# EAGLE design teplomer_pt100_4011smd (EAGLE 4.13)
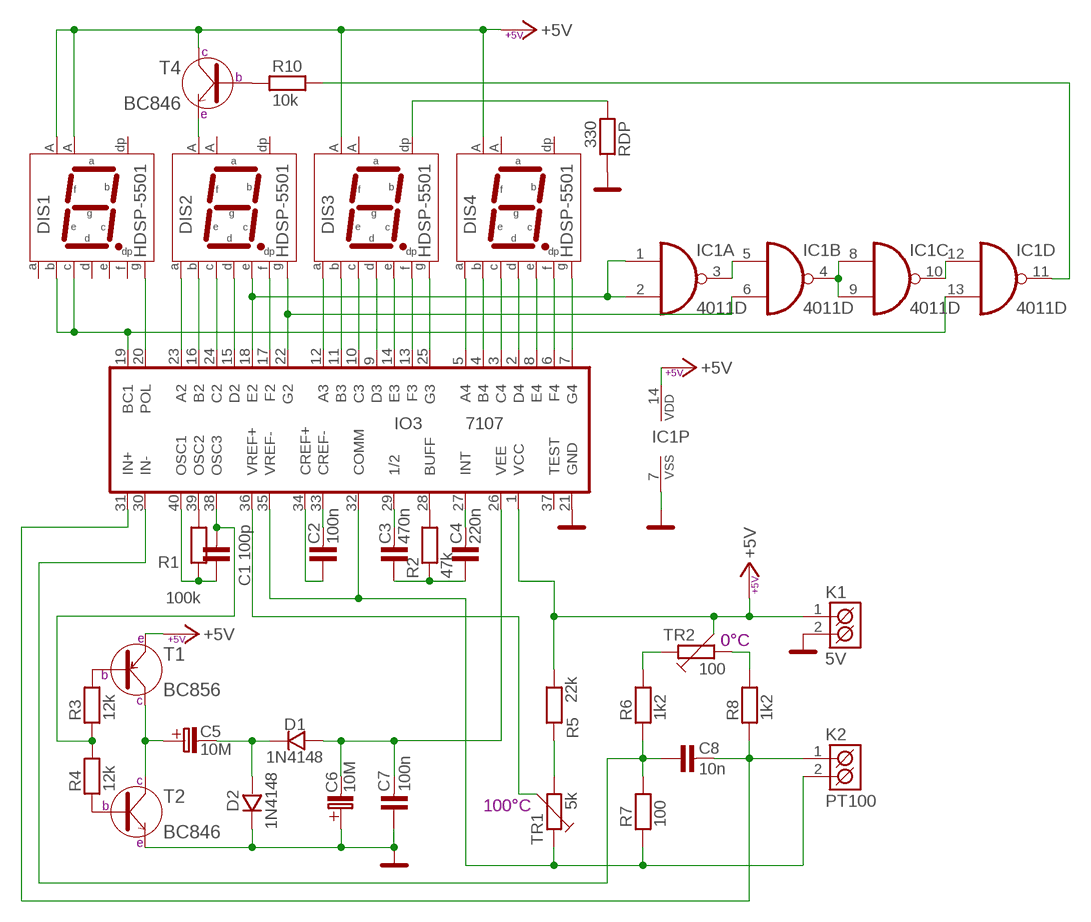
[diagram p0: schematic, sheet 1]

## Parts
C1  100p  C-KERAMIK_SMD_1206  [1206]
C2  100n  100N-J/63V  [RM5_2,5]
C3  470n  470N-J/63V  [RM5_3,2]
C4  220n  220N-J/63V  [RM5_3,2]
C5  10M  10M/25V  [C_EL_2]
C6  10M  10M/25V  [C_EL_2]
C7  100n  C-KERAMIK_SMD_1206  [1206]
C8  10n  C-KERAMIK_SMD_1206  [1206]
D1  1N4148  1N4148_SMD_SOD80  [SOD-80]
D2  1N4148  1N4148_SMD_SOD80  [SOD-80]
DIS1  HDSP-5501  [HDSP-M]
DIS2  HDSP-5501  [HDSP-M]
DIS3  HDSP-5501  [HDSP-M]
DIS4  HDSP-5501  [HDSP-M]
IC1  4011D  [SO14]
IO3  7107  [DIL40]
K1  5V  ARK500/2  [ARK500/2]
K2  PT100  ARK500/2  [ARK500/2]
R1  100k  R_SMD_1206  [1206]
R2  47k  R_SMD_1206  [1206]
R3  12k  R_SMD_1206  [1206]
R4  12k  R_SMD_1206  [1206]
R5  22k  R_SMD_1206  [1206]
R6  1k2  R_SMD_1206  [1206]
R7  100  R_SMD_1206  [1206]
R8  1k2  R_SMD_1206  [1206]
R10  10k  R_SMD_1206  [1206]
RDP  330  R_SMD_1206  [1206]
T1  BC856  [SOT-23]
T2  BC846  [SOT-23]
T4  BC846  [SOT-23]
TR1  5k  TRIMR64P  [64P]
TR2  100  TRIMR64P  [64P]

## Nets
+5V: DIS1.3(CA1) DIS1.8(CA2) DIS3.3(CA1) DIS4.3(CA1) IC1.14(P:VDD) IO3.1(VCC) K1.1(K1) R5.2 T1.1(E) T4.3(C) TR2.2
ANOD: IC1.11(D:O) R10.2
GND: C6.C+(C_EL+) C7.1 D2.K IC1.7(P:VSS) IO3.21(GND) K1.2(K2) RDP.2 T2.1(E)
N$1: IO3.39(OSC2) R1.2
N$2: C2.2 IO3.33(CREF-)
N$3: C1.2 IO3.38(OSC3) R3.1 R4.2
N$4: IO3.28(BUFF) R2.2
N$5: R3.2 T1.2(B)
N$6: R4.1 T2.2(B)
N$8: C5.C+(C_EL+) T1.3(C) T2.3(C)
N$9: IC1.10(C:O) IC1.12(D:I0)
N$10: DIS2.4(C) IO3.24(C2)
N$11: IC1.4(B:O) IC1.8(C:I0) IC1.9(C:I1)
N$12: C5.C-(C_EL-) D1.K D2.A
N$13: DIS2.6(B) IO3.16(B2)
N$14: IC1.3(A:O) IC1.5(B:I0)
N$16: R5.1 TR1.3
N$17: IO3.32(COMM) IO3.35(VREF-) K2.2(K2) R7.1 TR1.1
N$18: C8.1 IO3.30(IN-) R6.1 R7.2
N$19: R6.2 TR2.1
N$20: R8.2 TR2.3
N$21: C8.2 IO3.31(IN+) K2.1(K1) R8.1
N$23: C1.1 IO3.40(OSC1) R1.1
N$24: C2.1 IO3.34(CREF+)
N$25: C3.2 IO3.29(1/2)
N$26: C4.2 IO3.27(INT)
N$27: C3.1 C4.1 R2.1
N$29: IO3.36(VREF+) TR1.2
N$49: DIS2.7(A) IO3.23(A2)
N$50: DIS2.2(D) IO3.15(D2)
N$53: R10.1 T4.2(B)
N$54: DIS2.10(G) IC1.6(B:I1) IO3.22(G2)
N$55: DIS2.9(F) IO3.17(F2)
N$56: DIS3.4(C) IO3.10(C3)
N$57: DIS3.6(B) IO3.11(B3)
N$58: DIS3.7(A) IO3.12(A3)
N$59: DIS3.2(D) IO3.9(D3)
N$60: DIS3.1(E) IO3.14(E3)
N$61: DIS3.10(G) IO3.25(G3)
N$62: DIS3.9(F) IO3.13(F3)
N$63: DIS4.4(C) IO3.3(C4)
N$64: DIS4.6(B) IO3.4(B4)
N$65: DIS4.7(A) IO3.5(A4)
N$66: DIS4.2(D) IO3.2(D4)
N$67: DIS4.1(E) IO3.8(E4)
N$68: DIS4.10(G) IO3.7(G4)
N$69: DIS4.9(F) IO3.6(F4)
N$71: DIS1.4(C) DIS1.6(B) IC1.13(D:I1) IO3.19(BC1)
N$72: DIS1.10(G) IO3.20(POL)
N$74: DIS2.1(E) IC1.1(A:I0) IC1.2(A:I1) IO3.18(E2)
N$78: DIS2.3(CA1) T4.1(E)
N$79: DIS3.5(DP) RDP.1
VEE: C6.C-(C_EL-) C7.2 D1.A IO3.26(VEE)
Unconnected: DIS1.1(E) DIS1.2(D) DIS1.5(DP) DIS1.7(A) DIS1.9(F) DIS2.5(DP) DIS2.8(CA2) DIS3.8(CA2) DIS4.5(DP) DIS4.8(CA2) IO3.37(TEST)

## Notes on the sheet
- 0°C
- 100°C

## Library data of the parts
C1 C7 C8 = #PaJa_22:C-KERAMIK: Kondenzator - keramicky
C2 = #PaJa_C-folie:100N-J/63V
C3 = #PaJa_C-folie:470N-J/63V
C4 = #PaJa_C-folie:220N-J/63V
C5 C6 = #PaJa_C-el_2:10M/25V
D1 D2 = #PaJa_22:1N4148: Univerzalni dioda - 0,15A, 75V
DIS1-DIS4 = #PaJa_22:HDSP-5501: LED displej - SA - 14,2 mm - cervena
IC1 = 40xx:4011: Quad 2-input NAND
IO3 = #PaJa_22:7107: IO - A/D prevodnik + budic 7seg. displeje (3 a 1/2 mistny)
K1 K2 = #PaJa_22:ARK500/2: Svorkovnice - roztec 5mm - dvojita
R1-R8 R10 RDP = #PaJa_22:R: Rezistor
T1 = #PaJa_22:BC856: SMD tranzistor - PNP - ekv. BC556
T2 T4 = #PaJa_22:BC846: SMD tranzistor - NPN - ekv. BC546
TR1 TR2 = #PaJa_22:TRIMR: Trimr

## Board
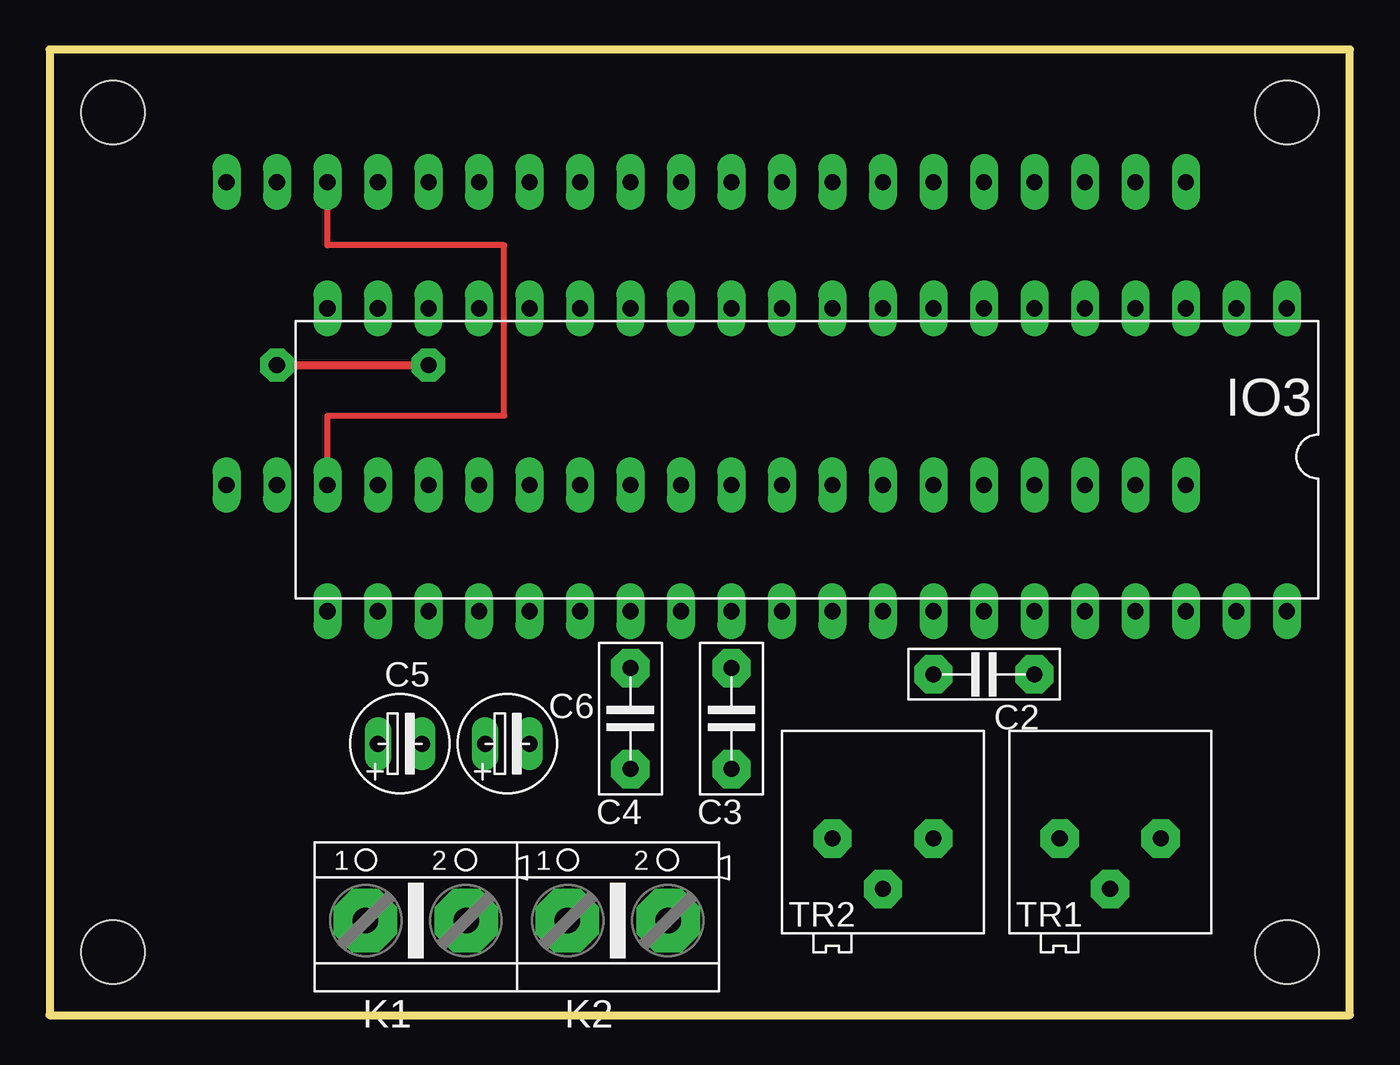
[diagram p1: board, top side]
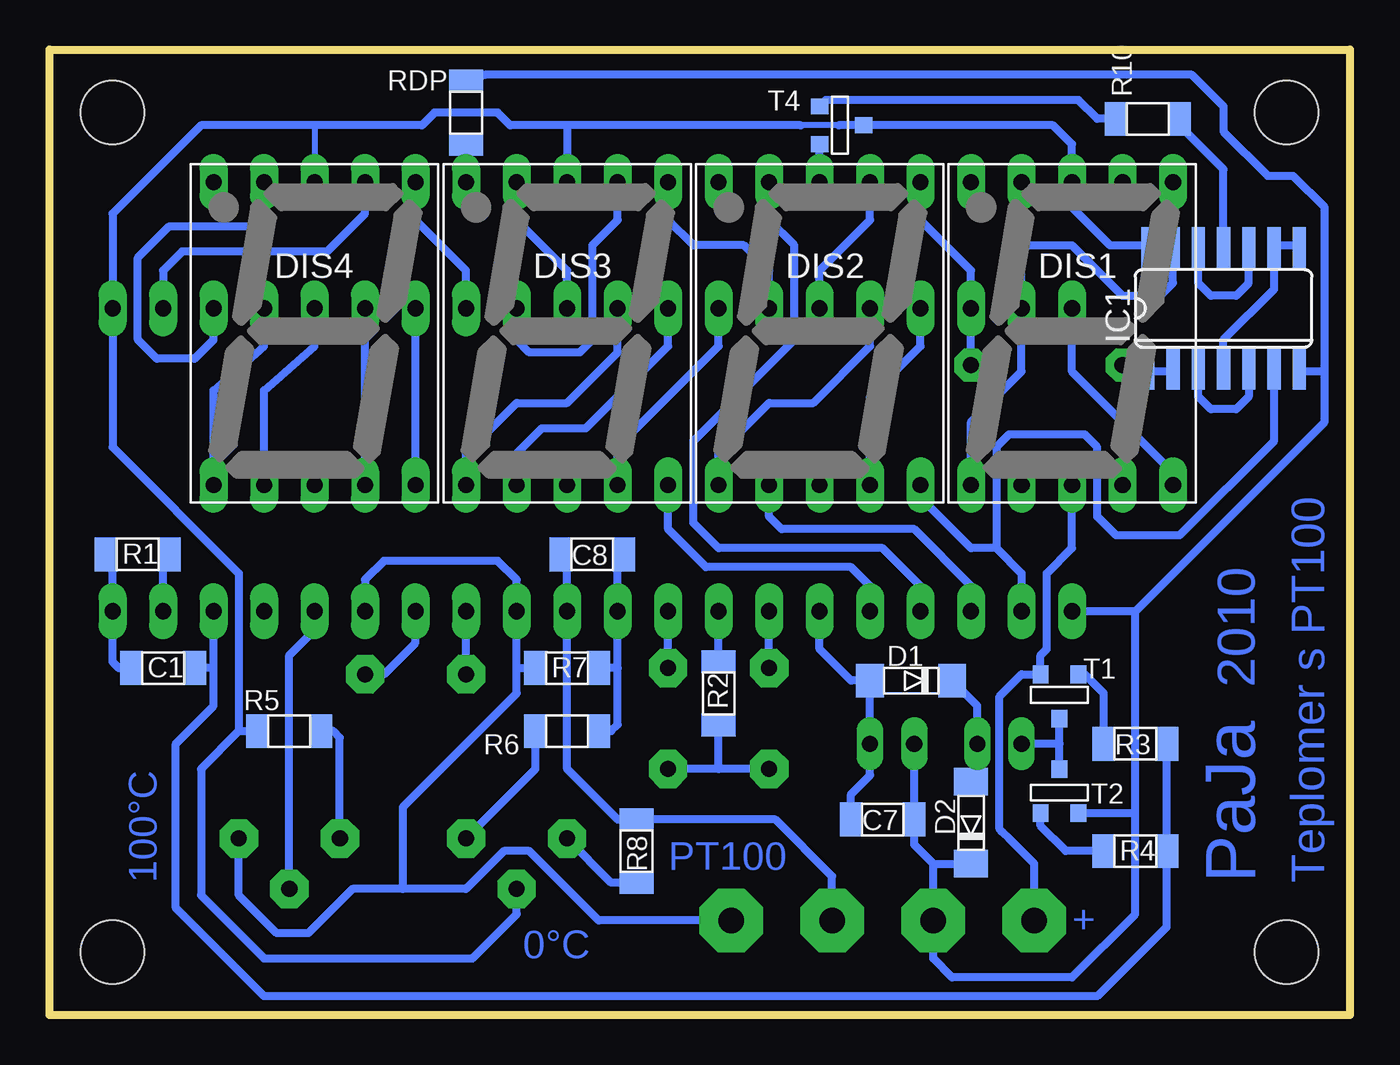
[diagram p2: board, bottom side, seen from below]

Size 65.39 x 48.57 mm. Coordinates in mm from the lower left corner, seen from the top.
Outline: 0,0 65.39,0 65.39,48.57 0,48.57 0,0
Copper layers (1*16): Top 0.035mm / dielectric 1.5mm / Bottom 0.035mm
Design rules "default": minimum track width 10mil, minimum drill 24mil, track to track 8mil, track to pad 8mil, pad to pad 8mil, via to via 8mil, smd to smd 8mil, copper to edge 40mil, drill to drill 8mil, minimum pad ring 10mil, minimum via ring 8mil, stop-mask expansion 4mil, vias tented up to drill 0mil, thermal gap 10mil
Holes 3.2 mm at 3.17,3.17 3.17,45.4 62.23,45.4 62.23,3.17

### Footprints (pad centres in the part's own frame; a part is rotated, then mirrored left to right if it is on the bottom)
1206 = smd 1.143 x 1.702: 1 -1.587,0; 2 1.587,0
RM5_2,5 = drill 0.813 pad 1.93 octagon: 1 -2.54,0; 2 2.54,0
RM5_3,2 = drill 0.813 pad 1.93 octagon: 1 -2.54,0; 2 2.54,0
C_EL_2 = drill 0.813 pad 1.27 long: C+ 0,0; C- 2.223,0
SOD-80 = smd 1.397 x 1.702: A 1.905,0; K -2.223,0
HDSP-M = drill 0.813 pad 1.4 long: 1 -5.08,-7.62; 2 -2.54,-7.62; 3 0,-7.62; 4 2.54,-7.62; 5 5.08,-7.62; 6 5.08,7.62; 7 2.54,7.62; 8 0,7.62; 9 -2.54,7.62; 10 -5.08,7.62
SO14 = smd 0.66 x 2.032: 1 -3.81,-3.073; 2 -2.54,-3.073; 3 -1.27,-3.073; 4 0,-3.073; 5 1.27,-3.073; 6 2.54,-3.073; 7 3.81,-3.073; 8 3.81,3.073; 9 2.54,3.073; 10 1.27,3.073; 11 0,3.073; 12 -1.27,3.073; 13 -2.54,3.073; 14 -3.81,3.073
DIL40 = drill 0.813 pad 1.4 long: 1 -22.86,-7.62; 2 -20.32,-7.62; 3 -17.78,-7.62; 4 -15.24,-7.62; 5 -12.7,-7.62; 6 -10.16,-7.62; 7 -7.62,-7.62; 8 -5.08,-7.62; 9 -2.54,-7.62; 10 0,-7.62; 11 2.54,-7.62; 12 5.08,-7.62; 13 7.62,-7.62; 14 10.16,-7.62; 15 12.7,-7.62; 16 15.24,-7.62; 17 17.78,-7.62; 18 20.32,-7.62; 19 22.86,-7.62; 20 25.4,-7.62; 21 25.4,7.62; 22 22.86,7.62; 23 20.32,7.62; 24 17.78,7.62; 25 15.24,7.62; 26 12.7,7.62; 27 10.16,7.62; 28 7.62,7.62; 29 5.08,7.62; 30 2.54,7.62; 31 0,7.62; 32 -2.54,7.62; 33 -5.08,7.62; 34 -7.62,7.62; 35 -10.16,7.62; 36 -12.7,7.62; 37 -15.24,7.62; 38 -17.78,7.62; 39 -20.32,7.62; 40 -22.86,7.62
ARK500/2 = drill 1.27 pad 3.2 octagon: 1 -2.54,0; 2 2.54,0
SOT-23 = smd 0.787 x 0.889: 1 0.953,-0.953; 2 -0.953,-0.953; 3 0,1.27
64P = drill 0.813 pad 1.93 octagon: 1 0,2.54; 2 2.54,0; 3 0,-2.54

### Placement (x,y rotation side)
C1  59.69,17.46 0 bottom
C2  46.99,17.14 180 top
C3  34.29,14.92 90 top
C4  29.21,14.92 90 top
C5  16.51,13.65 0 top
C6  21.91,13.65 0 top
C7  23.5,9.84 180 bottom
C8  38.1,23.18 180 bottom
D1  22.23,16.83 180 bottom
D2  19.05,9.84 90 bottom
DIS1  13.97,34.29 180 bottom
DIS2  26.67,34.29 180 bottom
DIS3  39.37,34.29 180 bottom
DIS4  52.07,34.29 180 bottom
IC1  6.35,35.56 0 bottom
IO3  39.37,27.94 180 top
K1  18.41,4.76 0 top
K2  28.57,4.76 0 top
R1  60.96,23.18 0 bottom
R2  31.75,16.19 90 bottom
R3  10.79,13.65 180 bottom
R4  10.79,8.26 0 bottom
R5  53.34,14.29 180 bottom
R6  39.37,14.29 180 bottom
R7  39.37,17.46 0 bottom
R8  35.88,8.26 270 bottom
R10  10.16,45.09 0 bottom
RDP  44.45,45.4 90 bottom
T1  14.61,16.19 180 bottom
T2  14.61,11.11 0 bottom
T4  25.72,44.77 270 bottom
TR1  53.34,8.89 270 top
TR2  41.91,8.89 270 top

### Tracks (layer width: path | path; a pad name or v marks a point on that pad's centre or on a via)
+5V
  Top 0.305: DIS1.8 13.97,30.16 22.86,30.16 22.86,38.73 13.97,38.73 DIS1.3
  Bottom 0.305: 25.72,44.77 27.62,44.77 | 52.07,44.77 DIS4.3
  Bottom 0.406: 39.37,44.77 42.23,44.77 42.86,45.4 46.04,45.4 46.67,44.77 52.07,44.77 57.78,44.77 62.23,40.32 IO3.1 62.23,28.57 55.88,22.23 55.88,14.29 | 17.14,8.89 17.46,9.21 17.62,9.37 17.62,16.03 16.51,17.14 T1.1 15.56,18.1 15.24,18.41 15.24,22.23 13.97,23.5 DIS1.8 | 17.14,8.89 | 17.14,8.89 15.88,7.62 K1.1 | 25.72,44.77 T4.3 14.92,44.77 13.97,43.81 DIS1.3 13.97,40.64 12.06,38.73 10.26,38.73 IC1.14 | 27.62,44.77 39.37,44.77 | 39.37,44.77 DIS3.3 | TR2.2 41.91,5.08 44.13,2.86 54.61,2.86 57.78,6.03 57.78,12.38 55.88,14.29 | 55.88,14.29 R5.2
ANOD
  Bottom 0.406: R10.2 8.57,44.77 6.35,42.55 IC1.11
GND
  Bottom 0.406: 10.79,10.16 T2.1 | C6.C+ C7.1 21.91,8.57 20.95,7.62 | RDP.2 43.5,47.31 7.94,47.31 6.35,45.72 6.35,44.45 4.13,42.23 2.86,42.23 1.27,40.64 1.27,32.38 | 10.79,20.32 IO3.21 | 10.79,10.16 10.79,20.32 | 10.79,10.16 10.79,5.08 13.97,1.91 20,1.91 20.95,2.86 K1.2 20.95,7.62 | 20.95,7.62 D2.K | IC1.7 2.44,32.38 1.27,32.38 | 10.79,20.32 1.27,29.84 1.27,32.38
N$1
  Bottom 0.406: R1.2 59.69,22.86 IO3.39
N$2
  Bottom 0.406: C2.2 IO3.33
N$3
  Bottom 0.406: 57.15,17.46 IO3.38 | R3.1 R4.2 9.21,4.45 12.7,0.95 54.61,0.95 59.05,5.4 59.05,13.65 57.15,15.56 57.15,17.46 | 57.15,17.46 C1.2
N$4
  Bottom 0.406: R2.2 IO3.28
N$5
  Bottom 0.406: R3.2 12.38,16.19 13.34,17.14 T1.2
N$6
  Bottom 0.406: R4.1 14.29,8.26 15.56,9.53 T2.2
N$8
  Bottom 0.406: 14.61,13.65 C5.C+ | T2.3 14.61,13.65 | 14.61,13.65 T1.3
N$9
  Bottom 0.406: IC1.12 7.62,36.83 6.99,36.2 5.71,36.2 5.08,36.83 IC1.10 5.08,38.73
N$10
  Bottom 0.406: IO3.24 21.59,21.59 23.5,23.5 31.75,23.5 33.02,24.77 33.02,28.89 27.94,33.97 27.94,38.73 29.21,40.01 DIS2.4
N$11
  Bottom 0.406: IC1.4 6.35,33.97 3.81,36.51 IC1.9 3.81,38.73 2.64,38.73 IC1.8
N$12
  Bottom 0.406: D1.K 18.73,15.56 C5.C- 18.73,11.75 D2.A
N$13
  Bottom 0.406: IO3.16 24.13,33.66 26.99,30.8 29.21,30.8 31.75,28.26 DIS2.6
N$14
  Bottom 0.406: IC1.3 7.62,31.11 6.99,30.48 5.71,30.48 5.08,31.11 IC1.5
N$16
  Bottom 0.406: R5.1 51.12,14.29 50.8,13.97 TR1.3
N$17
  Bottom 0.406: IO3.35 49.53,21.91 48.58,22.86 42.86,22.86 41.91,21.91 IO3.32 41.91,17.46 | 41.91,17.46 R7.1 | 41.91,17.46 41.91,16.19 47.62,10.48 47.62,6.35 | K2.2 37.78,4.76 41.27,8.26 42.55,8.26 44.45,6.35 47.62,6.35 | TR1.1 55.88,6.03 53.98,4.13 52.39,4.13 50.16,6.35 47.62,6.35
N$18
  Bottom 0.406: 36.83,17.46 R7.2 | 36.83,17.46 IO3.30 36.83,23.18 C8.1 | R6.1 37.15,14.29 36.83,14.61 36.83,17.46
N$19
  Bottom 0.406: R6.2 40.96,12.38 TR2.1
N$20
  Bottom 0.406: R8.2 37.15,6.67 TR2.3
N$21
  Bottom 0.406: C8.2 39.37,23.18 IO3.31 39.37,12.38 36.83,9.84 R8.1 28.89,9.84 26.04,6.99 K2.1
N$23
  Bottom 0.406: R1.1 62.23,23.18 IO3.40 62.23,17.78 61.91,17.46 C1.1
N$24
  Bottom 0.406: C2.1 48.58,17.14 46.99,18.73 IO3.34
N$25
  Bottom 0.406: C3.2 IO3.29
N$26
  Bottom 0.406: C4.2 IO3.27
N$27
  Bottom 0.406: 31.75,12.38 R2.1 | C4.1 31.75,12.38 | 31.75,12.38 C3.1
N$29
  Bottom 0.406: TR1.2 53.34,18.1 52.07,19.37 IO3.36
N$49
  Bottom 0.406: IO3.23 19.05,21.59 21.91,24.45 28.57,24.45 29.21,25.08 DIS2.7
N$50
  Bottom 0.406: IO3.15 26.67,37.47 24.13,40.01 DIS2.2
N$53
  Bottom 0.406: T4.2 26.35,46.04 13.65,46.04 12.7,45.09 R10.1
N$54
  Bottom 0.406: DIS2.10 21.59,26.04 19.05,23.5 17.78,23.5 | 17.78,23.5 17.78,28.57 17.14,29.21 13.34,29.21 12.7,28.57 12.7,25.08 11.75,24.13 8.57,24.13 3.81,28.89 IC1.6 | 17.78,23.5 16.51,22.23 IO3.22
N$55
  Bottom 0.406: IO3.17 21.59,33.66 24.13,31.11 DIS2.9
N$56
  Bottom 0.406: IO3.10 39.37,37.47 41.91,40.01 DIS3.4
N$57
  Bottom 0.406: IO3.11 36.83,33.34 39.37,30.8 41.91,30.8 44.45,28.26 DIS3.6
N$58
  Bottom 0.406: IO3.12 34.29,33.66 38.42,29.53 40.64,29.53 41.91,28.26 DIS3.7
N$59
  Bottom 0.406: DIS3.2 36.83,40.01 38.1,38.73 38.1,33.97 38.73,33.34 41.27,33.34 41.91,33.97 IO3.9
N$60
  Bottom 0.406: IO3.14 29.21,37.47 30.48,38.73 33.02,38.73 34.29,40.01 DIS3.1
N$61
  Bottom 0.406: IO3.25 24.13,21.59 25.08,22.54 32.38,22.54 34.29,24.45 DIS3.10
N$62
  Bottom 0.406: IO3.13 31.75,33.66 36.83,28.57 DIS3.9
N$63
  Bottom 0.406: IO3.3 57.15,33.97 58.1,33.02 60.01,33.02 60.96,33.97 60.96,38.1 59.37,39.69 55.24,39.69 54.61,40.32 DIS4.4
N$64
  Bottom 0.406: DIS4.6 57.15,31.43 54.61,33.66 IO3.4
N$65
  Bottom 0.406: DIS4.7 54.61,31.43 52.07,33.66 IO3.5
N$66
  Bottom 0.406: DIS4.2 49.53,40.32 51.44,38.42 58.74,38.42 59.69,37.47 IO3.2
N$67
  Bottom 0.406: DIS4.1 46.99,40.01 44.45,37.47 IO3.8
N$68
  Bottom 0.406: DIS4.10 IO3.7
N$69
  Bottom 0.406: DIS4.9 IO3.6
N$71
  Bottom 0.406: 16.51,38.73 IO3.19 16.51,32.38 19.05,29.84 DIS1.6 | 16.51,38.73 DIS1.4 | 16.51,38.73 13.97,38.73 11.43,36.2 9.53,36.2 8.89,36.83 IC1.13
N$72
  Bottom 0.406: IO3.20 13.97,32.38 8.89,27.3 DIS1.10
N$74  (via drill 0.81 pad 1.68)
  Top 0.406: v11.43,32.7 v19.05,32.7
  Bottom 0.406: DIS2.1 21.59,40.01 19.05,37.47 IO3.18 v19.05,32.7 | IC1.2 8.99,32.38 10.16,32.38 IC1.1 10.26,32.38 11.11,32.38 v11.43,32.7
N$78
  Bottom 0.406: DIS2.3 T4.1
N$79
  Bottom 0.406: DIS3.5 RDP.1
VEE
  Bottom 0.406: C7.2 25.08,11.11 24.13,12.06 C6.C- D1.A 25.08,16.83 26.67,18.41 IO3.26

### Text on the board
Bottom: 2010 | Teplomer s PT100 | PaJa | PT100 | 100°C | + | 0°C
